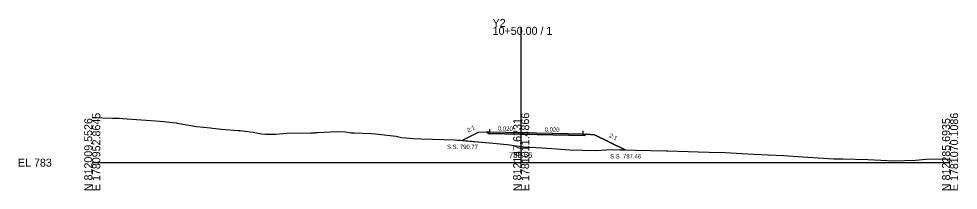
# Model space of a CAD drawing. Extents: x -26 to 303, y -10 to 3096.
# Drawn here: x -25.7 to 302.8, y 990.3 to 1050.4 of the extents above; entities that cross this region are included whole.
import ezdxf

# ---------------------------------------------------------------- set-up
doc = ezdxf.new("R2010")
doc.units = 0
for name, color, linetype in [('Exist Cross Section Cell', 7, 'Continuous'), ('Exist XS Center Line Elevation Label', 7, 'Continuous'), ('Exist XS Ground Line', 7, 'Continuous'), ('Prop XS Dump Level', 7, 'Continuous'), ('Prop XS Earthwork Shape', 7, 'Continuous'), ('Prop XS EOT Tick Mark', 7, 'Continuous'), ('Prop XS Finish Grade', 7, 'Continuous'), ('Prop XS Finish Grade Earthwork', 7, 'Continuous'), ('Prop XS Finish Grade Pavement', 7, 'Continuous'), ('Prop XS Pvmt Edge Slope', 7, 'Continuous'), ('Prop XS SE Text', 7, 'Continuous'), ('Prop XS Side Slope Text', 7, 'Continuous'), ('Prop XS SS Elevation Text', 7, 'Continuous'), ('Prop XS Subgrade Earthwork', 7, 'Continuous')]:
    doc.layers.add(name, color=color, linetype=linetype)

msp = doc.modelspace()

# ---------------------------------------------------------------- linework, layer by layer
at = {"layer": 'Exist Cross Section Cell'}
for p, q in [((150, 1000), (150, 1047.6)), ((0, 1000), (150, 1000)), ((150, 1000), (300, 1000))]:
    msp.add_line(p, q, dxfattribs=at)
at = {"layer": 'Exist XS Ground Line'}
for p, q in [((0, 1015.87), (7.11, 1015.63)), ((7.11, 1015.63), (9.37, 1015.56)), ((9.37, 1015.56), (10.62, 1015.52)), ((10.62, 1015.52), (23.72, 1014.52)), ((23.72, 1014.52), (29.32, 1013.89)), ((29.32, 1013.89), (29.69, 1013.85)), ((29.69, 1013.85), (36.49, 1012.65)), ((36.49, 1012.65), (41.39, 1012.17)), ((41.39, 1012.17), (42.03, 1012.11)), ((42.03, 1012.11), (44.12, 1011.89)), ((44.12, 1011.89), (45.06, 1011.72)), ((45.06, 1011.72), (51.08, 1011.28)), ((51.08, 1011.28), (51.75, 1011.29)), ((51.75, 1011.29), (55.28, 1010.81)), ((55.28, 1010.81), (56.25, 1010.72)), ((56.25, 1010.72), (59.23, 1010.11)), ((59.23, 1010.11), (60.55, 1010)), ((60.55, 1010), (64.25, 1009.98)), ((64.25, 1009.98), (66.6, 1010.24)), ((66.6, 1010.24), (68.03, 1010.35)), ((68.03, 1010.35), (76.43, 1010.46)), ((76.43, 1010.46), (77.79, 1010.5)), ((77.79, 1010.5), (78.12, 1010.52)), ((78.12, 1010.52), (78.77, 1010.56)), ((78.77, 1010.56), (85.61, 1010.91)), ((85.61, 1010.91), (88.39, 1010.75)), ((88.39, 1010.75), (90.58, 1010.46)), ((90.58, 1010.46), (91.68, 1010.43)), ((91.68, 1010.43), (97.45, 1010.16)), ((97.45, 1010.16), (99.05, 1010.1)), ((99.05, 1010.1), (103.16, 1009.6)), ((103.16, 1009.6), (106.33, 1009.22)), ((106.33, 1009.22), (108.17, 1008.82)), ((108.17, 1008.82), (112.4, 1008.48)), ((112.4, 1008.48), (115.05, 1008.36)), ((115.05, 1008.36), (126.91, 1007.95)), ((126.91, 1007.95), (127.77, 1007.88)), ((127.77, 1007.88), (128.81, 1007.82)), ((128.81, 1007.82), (138.88, 1006.9)), ((138.88, 1006.9), (145.12, 1006.34)), ((145.12, 1006.34), (150, 1005.66)), ((150, 1005.66), (150.8, 1005.55)), ((150.8, 1005.55), (157.39, 1005.22)), ((157.39, 1005.22), (162.33, 1004.81)), ((162.33, 1004.81), (166.94, 1004.43)), ((166.94, 1004.43), (176.19, 1004.26)), ((176.19, 1004.26), (181.43, 1004.61)), ((181.43, 1004.61), (184.52, 1004.5)), ((184.52, 1004.5), (200.77, 1004.18)), ((200.77, 1004.18), (201.33, 1004.17)), ((201.33, 1004.17), (211.95, 1003.8)), ((211.95, 1003.8), (215.75, 1003.66)), ((215.75, 1003.66), (221.37, 1003.49)), ((221.37, 1003.49), (231.21, 1002.95)), ((231.21, 1002.95), (241.75, 1002.44)), ((241.75, 1002.44), (250.2, 1001.94)), ((250.2, 1001.94), (259.29, 1001.38)), ((259.29, 1001.38), (262.46, 1001.29)), ((262.46, 1001.29), (271.26, 1001.07)), ((271.26, 1001.07), (280.3, 1000.62)), ((280.3, 1000.62), (287.9, 1000.86)), ((287.9, 1000.86), (291.62, 1001.2)), ((291.62, 1001.2), (299.52, 1001.36)), ((299.52, 1001.36), (300, 1001.38))]:
    msp.add_line(p, q, dxfattribs=at)
at = {"layer": 'Prop XS Dump Level'}
for p, q in [((139, 1010.77), (150, 1010.55)), ((150, 1010.55), (171.68, 1010.11))]:
    msp.add_line(p, q, dxfattribs=at)
at = {"layer": 'Prop XS Earthwork Shape'}
msp.add_lwpolyline([(129.33, 1007.77), (138.88, 1006.9), (145.12, 1006.34), (150, 1005.66), (150.8, 1005.55), (157.39, 1005.22), (162.33, 1004.81), (166.94, 1004.43), (176.19, 1004.26), (181.43, 1004.61), (184.52, 1004.5), (186.34, 1004.46), (175.68, 1009.79), (172.78, 1010.03), (172.27, 1009.52), (149.99, 1009.96), (138.43, 1010.19), (137.9, 1010.72), (135, 1010.61)], close=True, dxfattribs=at)
at = {"layer": 'Prop XS EOT Tick Mark'}
for p, q in [((139, 1010.77), (139, 1011.77)), ((171.68, 1010.11), (171.68, 1011.11))]:
    msp.add_line(p, q, dxfattribs=at)
at = {"layer": 'Prop XS Finish Grade'}
for p, q in [((139, 1010.77), (137.9, 1010.72)), ((171.68, 1010.11), (172.78, 1010.03))]:
    msp.add_line(p, q, dxfattribs=at)
at = {"layer": 'Prop XS Finish Grade Earthwork'}
for p, q in [((135, 1010.61), (129.33, 1007.77)), ((137.9, 1010.72), (135, 1010.61)), ((172.78, 1010.03), (175.68, 1009.79)), ((175.68, 1009.79), (186.34, 1004.46))]:
    msp.add_line(p, q, dxfattribs=at)
at = {"layer": 'Prop XS Finish Grade Pavement'}
for p, q in [((139, 1010.77), (150, 1010.55)), ((150, 1010.55), (171.68, 1010.11))]:
    msp.add_line(p, q, dxfattribs=at)
at = {"layer": 'Prop XS Pvmt Edge Slope'}
for p, q in [((139, 1010.77), (138.43, 1010.19)), ((171.68, 1010.11), (172.27, 1009.52))]:
    msp.add_line(p, q, dxfattribs=at)
at = {"layer": 'Prop XS Subgrade Earthwork'}
for p, q in [((138.43, 1010.19), (137.9, 1010.72)), ((138.43, 1010.19), (149.99, 1009.96)), ((149.99, 1009.96), (172.27, 1009.52)), ((172.27, 1009.52), (172.78, 1010.03))]:
    msp.add_line(p, q, dxfattribs=at)

# ---------------------------------------------------------------- texts
at = {"layer": 'Exist Cross Section Cell'}
for s, p in [('Y2', (140, 1047.6)), ('10+50.00 / 1', (140, 1044.8)), ('EL 783', (-26, 998.6))]:
    msp.add_text(s, height=2.8, dxfattribs=at).set_placement(p)
for s, p in [('N 812009.5526', (0, 990)), ('E 1780952.8645', (2.8, 990)), ('N 812147.6231', (150, 990)), ('E 1781011.4866', (152.8, 990)), ('N 812285.6935', (300, 990)), ('E 1781070.1086', (302.8, 990))]:
    msp.add_text(s, height=2.8, rotation=90, dxfattribs=at).set_placement(p)
at = {"layer": 'Exist XS Center Line Elevation Label'}
msp.add_text('788.66', height=2, dxfattribs=at).set_placement((145.73, 1001.66))
at = {"layer": 'Prop XS Dump Level'}
for p in [(135, 1010.57), (175.68, 1009.75)]:
    msp.add_text('Case1', height=0.04, dxfattribs=at).set_placement(p)
at = {"layer": 'Prop XS SE Text'}
for p in [(141.88, 1011.21), (158.21, 1010.88)]:
    msp.add_text('0.020', height=1.5, rotation=358.8542, dxfattribs=at).set_placement(p)
at = {"layer": 'Prop XS Side Slope Text'}
for rotation, p in [(26.5651, (131.49, 1010.53)), (333.4349, (180.6, 1009.01))]:
    msp.add_text('2:1', height=1.5, rotation=rotation, dxfattribs=at).set_placement(p)
at = {"layer": 'Prop XS SS Elevation Text'}
for s, p in [('S.S. 790.77', (124.07, 1004.77)), ('S.S. 787.46', (181.12, 1001.46))]:
    msp.add_text(s, height=1.5, dxfattribs=at).set_placement(p)

doc.saveas('drawing.dxf')
